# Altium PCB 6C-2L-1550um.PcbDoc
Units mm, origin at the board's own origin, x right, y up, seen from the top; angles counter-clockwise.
Board outline 17.5 x 20 mm, 2 copper layers (Top Layer, Bottom Layer), stack 1.586 mm thick; 22 components, 13 nets, 82 pads, 16 vias.
Unrouted connection lines stored in the file: 1.
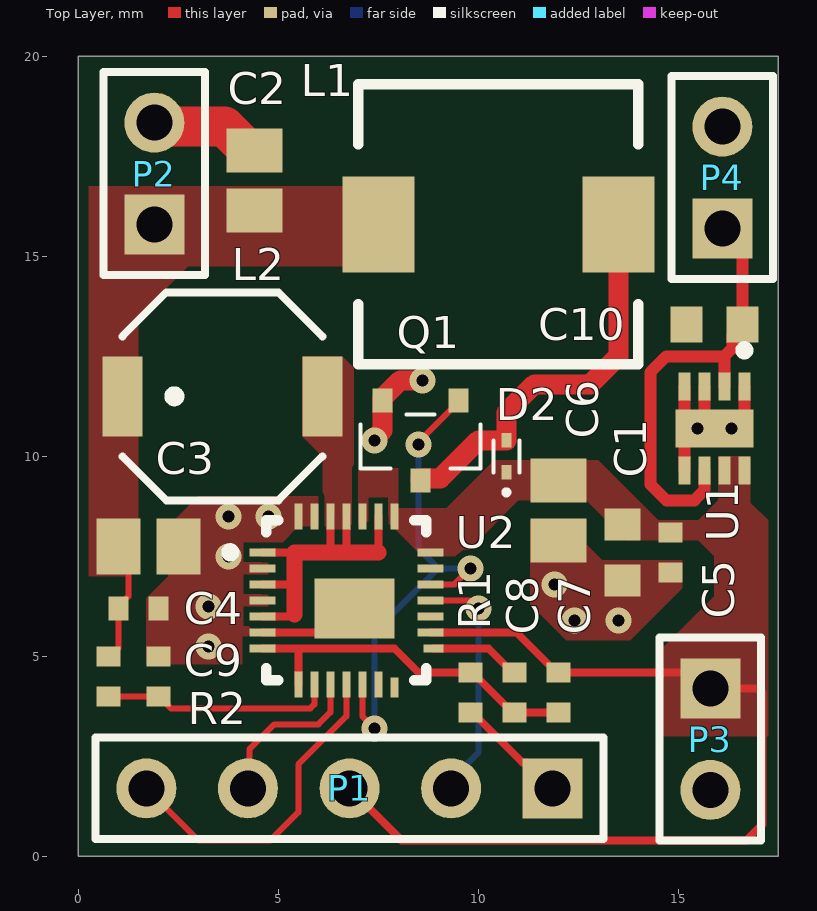
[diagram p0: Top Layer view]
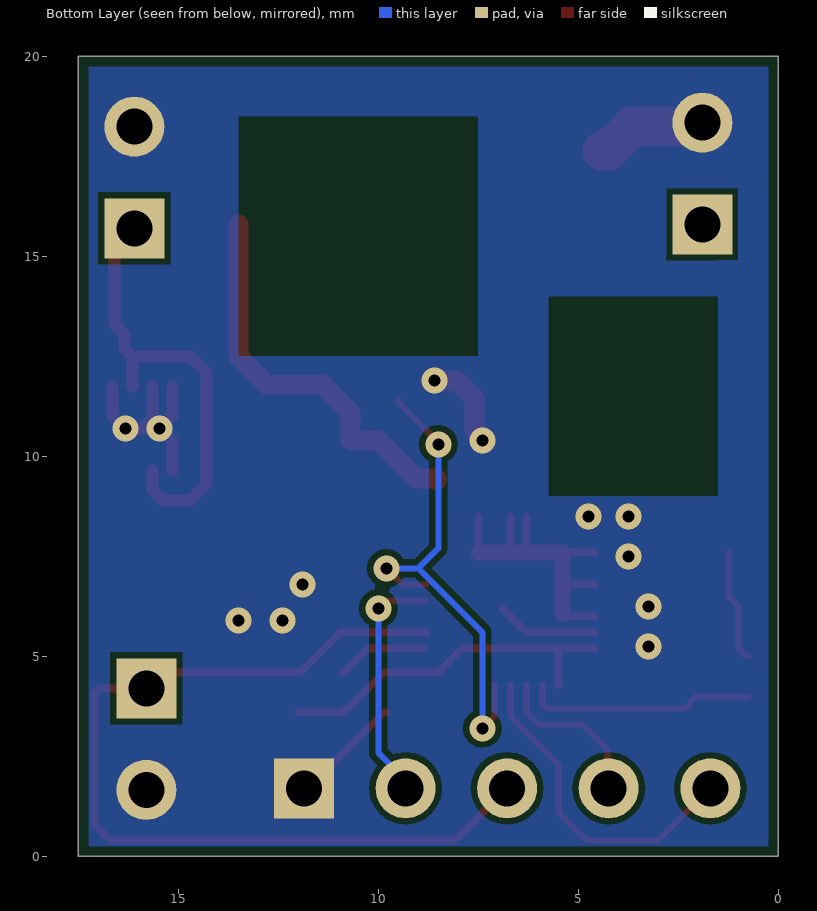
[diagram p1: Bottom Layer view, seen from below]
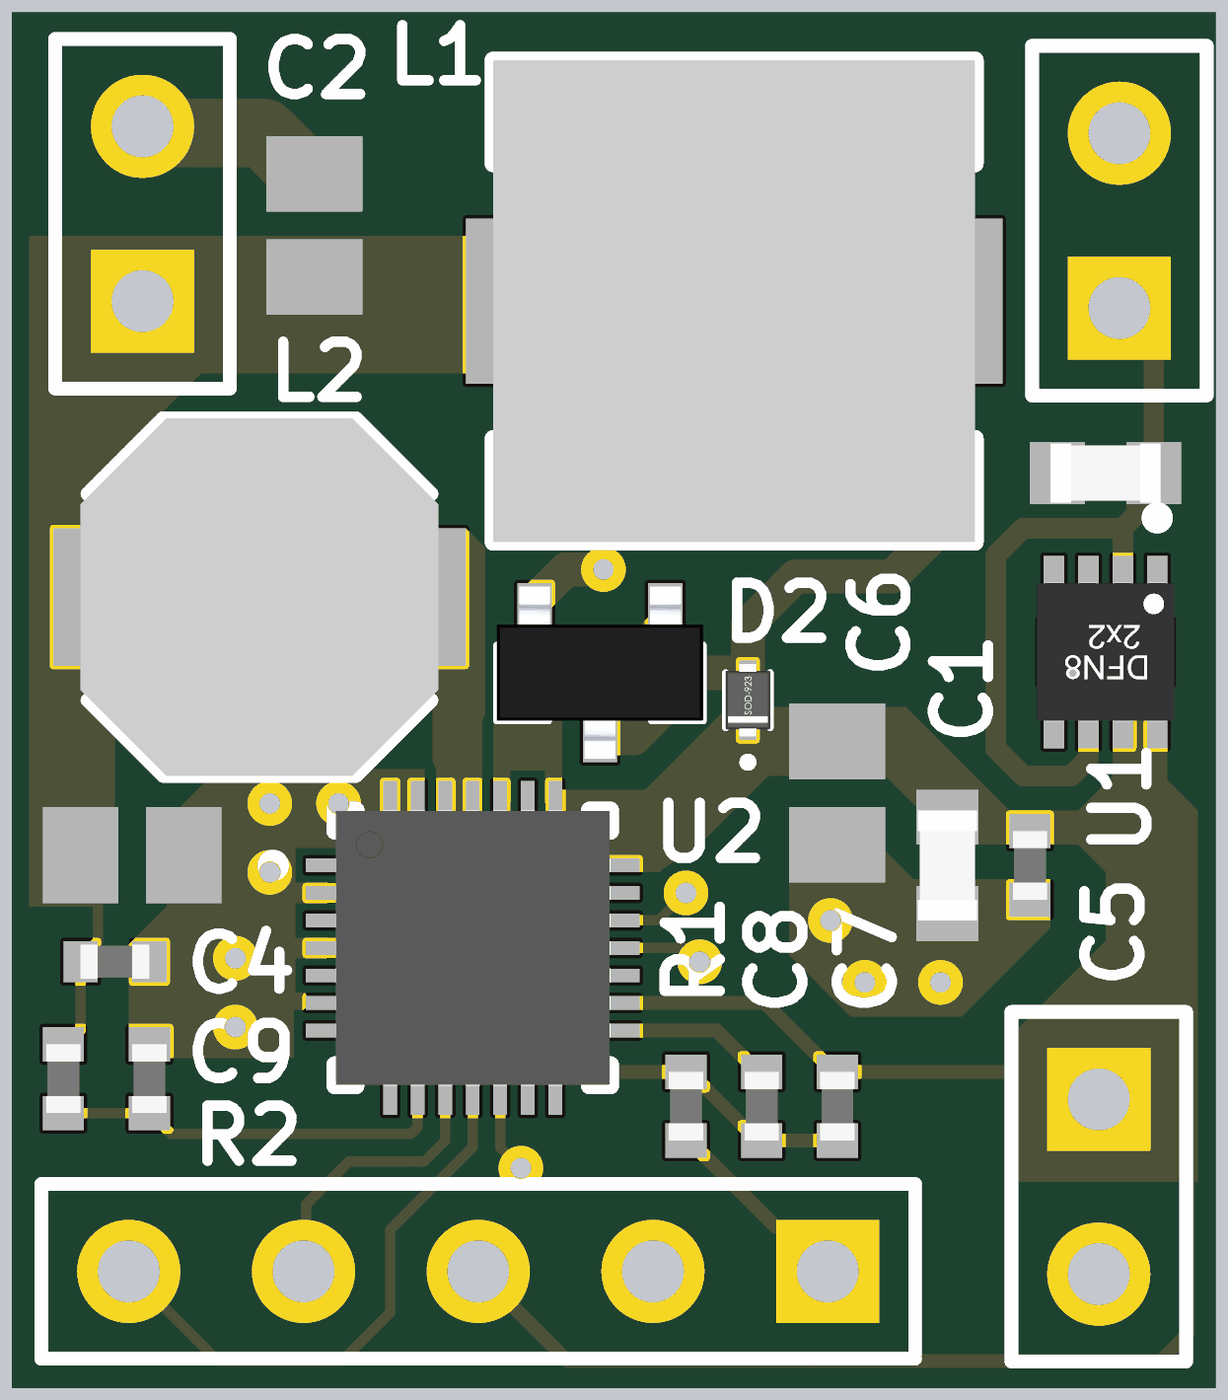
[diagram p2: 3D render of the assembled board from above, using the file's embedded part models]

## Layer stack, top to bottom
Top Solder: solder mask 0.0102, Solder Resist, Dk 3.5
Top Layer: signal copper 0.018
Dielectric1: core 1.55, FR-4, Dk 4.8
Bottom Layer: signal copper 0.018
Bottom Solder: solder mask 0.0102, Solder Resist, Dk 3.5

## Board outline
0,0 17.5,0 17.5,20 0,20

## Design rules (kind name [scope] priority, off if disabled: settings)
BoardOutlineClearance [All] p1: gap=0.25 ignorepadtopadclearanceinfootprint=FALSE except(0: Arc-SplitContinuation Track-SplitContinuation SMDPad-SplitContinuation THPad-SplitContinuation Via-SplitContinuation Fill-SplitContinuation Poly-SplitContinuation Region-SplitContinuation Text-SplitContinuation)
Clearance Clearance-xPP-xTP-xTT [All] p1: gap=0.15 ignorepadtopadclearanceinfootprint=FALSE except(0: Arc-Hole Track-Hole SMDPad-Hole THPad-Hole Via-Hole Fill-Hole Poly-Hole Region-Hole Text-Hole)
ComponentClearance [All] p1: gap=0.25 collisioncheckmode=3 verticalgap=0.25 showdistances=FALSE
DiffPairsRouting [All] p1: maxlimit=0.25 minlimit=0.25 mostfreqgap=0.25 toplayer_minwidth=0.381 toplayer_maxwidth=0.381 toplayer_prefwidth=0.381 bottomlayer_minwidth=0.381 bottomlayer_maxwidth=0.381 bottomlayer_prefwidth=0.381 maxuncoupledlength=12.5
Height [All] p1: minheight=0 maxheight=25 prefheight=12.5
HoleSize HoleSize-PTH [All] p1: absolutevalues=TRUE maxlimit=2 minlimit=0.25 maxpercent=80.000 minpercent=20.000
HoleToHoleClearance [All] p1: gap=0.35 allowstackedmicrovias=TRUE
MinimumAnnularRing "Minimum IAR  >0.45mm" [((ObjectKind = 'Pad') OR (ObjectKind = 'Via')) And (Layer = 'MultiLayer') And (HoleDiameter > AsMM(0.45))] p1: minimumring=0.175 // minimum inner annular ring for pads > 0.45mm finished hole size
MinimumAnnularRing "Minimum IAR <=0.45mm" [((ObjectKind = 'Pad') OR (ObjectKind = 'Via')) And (Layer = 'MultiLayer') And (HoleDiameter <= AsMM(0.45))] p2: minimumring=0.175 // minimum inner annular ring for pads <= 0.45mm finished hole size
MinimumSolderMaskSliver [All] p1: minsoldermaskwidth=0.08
PlaneClearance PlaneClearance-IPI [All] p1: clearance=0.25
PlaneConnect [All] p1: planeconnectstyle=Relief reliefexpansion=0.175 reliefentries=4 reliefconductorwidth=0.2 reliefairgap=0.2
PolygonConnect PolygonConnect-xTW [All] p1: connectstyle=Direct reliefconductorwidth=0.2 reliefentries=4 polygonreliefangle="90 Angle" airgapwidth=0.2
RoutingCorners [All] p1: cornerstyle=45-Degree minsetback=2.5 maxsetback=2.5
RoutingVias "RoutingVias <= 0.45mm" [(ObjectKind = 'Via') And (HoleDiameter <= AsMM(0.45))] p1: holewidth=0.3 width=0.65 viastyle="Through Hole" minholewidth=0.25 minwidth=0.6 maxholewidth=0.45 maxwidth=0.8 // finishet hole size <= 0.45mm
RoutingVias "RoutingVias > 0.45mm" [(ObjectKind = 'Via') And (HoleDiameter > AsMM(0.45))] p2: holewidth=0.5 width=0.85 viastyle="Through Hole" minholewidth=0.5 minwidth=0.85 maxholewidth=0.9 maxwidth=1.25 // finishet hole size > 0.45mm
SilkToSilkClearance [All] p1: silktosilkclearance=0.2
SilkToSolderMaskClearance SilkscreenOverComponentPads [IsPad] p1: minsilkscreentomaskgap=0.2 clearancetoexposedcopper=TRUE
SolderMaskExpansion [All] p1: expansion=0 istentingtop=FALSE
UnRoutedNet [All] p1: checkbadconnections=TRUE
Width Width-xTW [All] p1: maxlimit=1.5 minlimit=0.15 preferedwidth=0.2
18 further rules are at their usual default settings.

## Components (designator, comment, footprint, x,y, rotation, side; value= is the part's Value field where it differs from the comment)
C1 "Cap_0603" 0603 13.6,7.6 r90 top value=2.2uF
C2 "Cap_0805" 0805 4.4,16.9 r270 top value=22uF
C3 "Cap_0805" 0805 1.75,7.75 r180 top value=22uF
C4 "Cap_0402" 0402 1.5,6.2 r180 top value=100nF
C5 "Cap_0402" 0402 14.8,7.6 r90 top value=100nF
C6 "Cap_0805" 0805 12,8.65 r90 top value=22uF
C7 "Cap_0402" 0402 12,4.1 r90 top value=100nF
C8 "Cap_0402" 0402 10.9,4.1 r90 top value=470nF
C9 "Cap_0402" 0402 2,4.5 r270 top value=100nF
C10 "Cap_0603" 0603 15.9,13.3 r0 top value=2.2uF
D2 "NSR0140P2" SOD-923 10.7,9.6 r90 top
L1 "SRR7045-102M" SRR7045-102M 7.5,15.8 r0 top value=X
L2 "SD53-4R7-R" SD53-4R7-R 3.6,11.5 r0 top value=X
P1 "Header 5" HDR1X5 11.86,1.7 r180 top
P2 "Header 2" HDR1X2 1.9,15.8 r90 top
P3 "Header 2" HDR1X2 15.8,4.2 r270 top
P4 "Header 2" HDR1X2 16.1,15.7 r90 top
Q1 "PMV130ENE" SOT-23 9.5,11.4 r180 top
R1 "Res_0402" 0402 9.8,4.1 r270 top value=0
R2 "Res_0402" 0402 0.75,4.5 r270 top value=51K
U1 "MCP1810" VDFN8 16.65,11.75 r270 top
U2 "Sunboost 3" 28-QFN_0.4mm 4.6,7.6 r0 top

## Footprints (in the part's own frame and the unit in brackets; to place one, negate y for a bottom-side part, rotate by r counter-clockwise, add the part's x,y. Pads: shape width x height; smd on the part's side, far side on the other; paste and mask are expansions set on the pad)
28-QFN_0.4mm [mm]
  rect 0.65x0.2 smd mask+0.05: 1(0,0) 2(0,-0.4) 3(0,-0.8) 4(0,-1.2) 5(0,-1.6) 6(0,-2) 7(0,-2.4) 16(4.2,-2) 17(4.2,-1.6) 18(4.2,-1.2) 19(4.2,-0.8) 20(4.2,-0.4) 21(4.2,0)
  rect 0.2x0.65 smd mask+0.05: 8(0.9,-3.3) 9(1.3,-3.3) 10(1.7,-3.3) 11(2.1,-3.3) 12(2.5,-3.3) 13(2.9,-3.3) 22(3.3,0.9) 23(2.9,0.9) 24(2.5,0.9) 25(2.1,0.9) 26(1.7,0.9) 27(1.3,0.9) 28(0.9,0.9)
  rect 0.2x0.5 smd mask+0.05: 14(3.3,-3.375)
  rect 0.5x0.2 smd mask+0.05: 15(4.275,-2.4)
  rect 2x1.5 smd mask+0.05: 29(2.3,-1.4)
  silkscreen extent -0.9,-3.2 4.1,0.8, body extent 0.1,-3.2 4.1,0.8, height 0.75
0402 [mm]
  rect 0.5x0.6 smd mask+0.05: 1(-0.5,0) 2(0.5,0)
  body extent -0.5,-0.25 0.5,0.25, height 0.25
0603 [mm] "0603 footprint"
  rect 0.8x0.9 smd: 1(-0.7,0) 2(0.7,0)
  body extent -0.8,-0.43 0.8,0.43, height 0.48
0805 [mm] "Chip Capacitor, Body 2.0x1.3mm, IPC High Density"
  rect 1.1x1.4 smd: 1(-0.75,0) 2(0.75,0)
  body extent -1.1,-0.72 1.1,0.72, height 1.4
HDR1X2 [mm] "Connector; Header; 2 Position"
  rect 1.5x1.5 hole 0.9: 1(0,0)
  round 1.5 hole 0.9: 2(2.54,0)
  silkscreen extent -1.27,-1.27 3.81,1.27
HDR1X5 [mm] "Connector; Header; 5 Position"
  rect 1.5x1.5 hole 0.9: 1(0,0)
  round 1.5 hole 0.9: 2(2.54,0) 3(5.08,0) 4(7.62,0) 5(10.16,0)
  silkscreen extent -1.27,-1.27 11.43,1.27
SD53-4R7-R [mm]
  rect 1x2 smd mask+0.05: 1(-2.5,0) 2(2.5,0)
  silkscreen extent -2.5,-2.6 2.5,2.6, body extent -2.6,-2.6 2.6,2.6, height 3
SOD-923 [mm]
  rect 0.36x0.25 smd mask+0.05: 1(0,0) 2(0.8,0)
  silkscreen extent -0.52,-0.33 0.8,0.33, body extent -0.12,-0.32 0.93,0.32, height 0.43
SOT-23 [mm]
  rect 0.5x0.6 smd mask+0.05: 1(0,0) 2(1.9,0) 3(0.95,2)
  silkscreen extent -0.55,0.35 2.45,1.7, body extent -0.55,-0.25 2.45,2.25, height 1.1
SRR7045-102M [mm]
  rect 1.8x2.4 smd mask+0.05: 1(0,0) 2(6,0)
  silkscreen extent -0.5,-3.5 6.5,3.5, body extent -0.5,-3.5 6.5,3.5, height 4.5
VDFN8 [mm] "2x2mm"
  rect 0.7x0.3 smd mask+0.05: 1(0,0) 2(0,-0.5) 3(0,-1) 4(0,-1.5) 5(2.1,-1.5) 6(2.1,-1) 7(2.1,-0.5) 8(2.1,0)
  rect 0.95x1.95 smd mask+0.05: 9(1.05,-0.75)
  silkscreen extent -1,-0.1 -0.8,0.1, body extent 0.04,-1.75 2.06,0.25, height 0.95

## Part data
C1 C2 C3 C4 C5 C6 C7 C8 C9 C10: "Capacitor"
D2: "Typical INFRARED GaAs LED"
L1 L2: "Inductor"
P1: "Header, 5-Pin"
P2 P3 P4: "Header, 2-Pin"
Q1: "N-Channel MOSFET"
R1 R2: "Resistor"
U1: "3V Regulator, 150 mA"
U2: "Initvation Sunboost 3"

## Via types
v1: diameter 0.65, hole 0.3, Top Layer to Bottom Layer, 16 vias

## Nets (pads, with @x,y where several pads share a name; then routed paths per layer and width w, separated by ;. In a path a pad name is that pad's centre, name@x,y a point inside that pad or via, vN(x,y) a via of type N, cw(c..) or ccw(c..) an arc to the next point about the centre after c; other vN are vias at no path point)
DGND: C7.1 C8.1 R1.1 U2.7 U2.8 | length 9
  Top Layer w0.2: U2.7 5.5,5.2 ; U2.8 5.5,5.2 ; C7.1 C8.1 10.75,3.75 10.7,3.75 9.85,4.6 R1.1 8.5,4.6 7.9,5.2 5.5,5.2
GND: C1.1 C2.1 C3.1 C4.1 C5.1 C6.1 C9.1 C10.1 P1.1 P2.2 P3.2 P4.2 Q1.2 R1.2 U1.1 U1.3 U1.4 U1.5 U1.9 U2.2 U2.4 U2.6 U2.27 U2.28 U2.29 | length 16.1
  Top Layer w0.2: U2.6 6.3,5.6 U2.29 ; R1.2 9.85,3.6 11.1,2.35 11.21,2.35 P1.1
  Top Layer w0.3: U1.5 15.15,10.375 v1(15.475,10.7) ; U1.4 15.15,11.025 v1(15.475,10.7) ; U1.3 15.65,10.95 U1.9 ; U1.1 16.65,11.025 v1(16.325,10.7) U1.9 ; v1(15.475,10.7) U1.9
  Top Layer w0.5: v1(7.4,10.4) 7.4,10.441 7.6,10.641 7.6,11.45 8.05,11.9 v1(8.6,11.9)
  Top Layer w1: P2.2 1.996,18.244 3.656,18.244 4.25,17.65 C2.1
  other v1: 3.25,5.25 12.4,5.9 13.5,5.9 3.25,6.25 11.9,6.8 3.75,7.5 3.75,8.5 4.75,8.5
ICSP: P1.2 U2.18 | length 6.1
  Top Layer w0.15: U2.18 9.8,6.4 v1(10,6.2)
  Bottom Layer w0.15: P1.2 9.32,1.91 10,2.59 v1(10,6.2)
ICSPCLK: P1.4 U2.10 | length 4.1
  Top Layer w0.15: P1.4 4.275,1.735 4.275,2.675 4.9,3.3 6,3.3 6.3,3.6 U2.10
ICSPDAT: P1.5 U2.11 | length 8.3
  Top Layer w0.15: P1.5 3,0.4 4.8,0.4 5.5,1.1 5.5,2.3 6.7,3.5 U2.11
NetC8_2: C8.2 U2.15 | length 2.3
  Top Layer w0.2: U2.15 10.25,5.2 10.85,4.6 C8.2
NetC9_2: C9.2 R2.2 U2.9 | length 5.8
  Top Layer w0.15: R2.2 2.05,4 2.225,3.825 2.225,3.788 2.313,3.7 5.8,3.7 5.9,3.8 U2.9
NetD2_2: D2.2 L1.2 Q1.3 | length 10
  Top Layer w0.5: Q1.3 8.55,9.45 9.05,9.45 10,10.4 D2.2 10.7,11.1 11.4,11.8 12.8,11.8 13.5,12.5 L1.2
NetL2_2: L2.2 U2.1 U2.3 U2.5 U2.23 U2.25 U2.26 | length 8.8
  Top Layer w0.2: U2.5 5.35,6 5.4,6.05 ; U2.3 5.4,6.8 ; U2.1 5.4,7.6 ; 6.3,7.6 U2.26 ; 6.7,7.6 U2.25 ; 7.5,7.6 U2.23
  Top Layer w0.4: 5.4,6.05 5.4,6.8 5.4,7.6 6.3,7.6 6.7,7.6 7.5,7.6
PWM: Q1.1 U2.12 U2.19 | length 12.7
  Top Layer w0.15: U2.12 7.1,3.5 v1(7.4,3.2) ; v1(8.5,10.3) 8.5,10.35 9.5,11.35 Q1.1 ; U2.19 9.4,6.8 v1(9.8,7.2)
  Bottom Layer w0.15: v1(7.4,3.2) 7.4,5.6 9,7.2 ; v1(8.5,10.3) 8.5,7.7 9,7.2 ; v1(9.8,7.2) 9,7.2
Solar+: C2.2 C3.2 C4.2 L1.1 L2.1 P2.1 R2.1 | length 2.8
  Top Layer w0.15: R2.1 0.8,5 1,5.2 C4.2 1,6.25 1.25,6.5 C3.2@1.25,7.6
VCC: C1.2 C5.2 C6.2 C7.2 D2.1 P1.3 P3.1 U1.7 U1.8 U2.16 U2.21 U2.22 U2.24 | length 23.2
  Top Layer w0.2: P1.3 8.08,0.4 16.7,0.4 17.1,0.8 17.1,4.083 16.983,4.2 P3.1 15.4,4.6 C7.2 11.95,4.6 10.95,5.6 U2.16
VDD: C10.2 P4.1 U1.2 U1.6 | length 11.3
  Top Layer w0.3: U1.6 15.65,9.15 15.4,8.9 14.7,8.9 14.3,9.3 14.3,12.1 14.7,12.5 16.15,12.5 ; P4.1 16.6,15.2 C10.2 16.35,13.05 16.35,12.7 16.15,12.5 ; U1.2 16.15,12.5
pads on no net: U2.13 U2.14 U2.17 U2.20

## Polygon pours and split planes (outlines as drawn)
NetL2_2 on Top Layer "NETL2_2_L01_P012" (solid, pour order 12): 6.6,12.5 6.882,12.218 6.882,8.176 6.115,8.176 6.115,9.985 5.6,10.5 5.6,12.5
GND on Top Layer "GND_L01_P011" (solid, pour order 11): 11.3,8.4 11.3,6.3 12.2,5.4 13.8,5.4 15.1,6.7 15.1,7.4 13.1,7.4 12.7,7.8 12.7,8.4
GND on Top Layer "GND_L01_P001" (solid, pour order 1): 2.25,8.25 2.25,7 1.75,6.5 1.75,6 2.5,6 3,5.5 4.75,5.5 4.75,7.5 5.5,8.25 6,8.25 6,9 3,9
VCC on Top Layer "VCC_L01_P005" (solid, pour order 5): 16,10 16.8,10 16.8,8.845 17.3,8.345 17.3,7.1 16.4,7.1 15.3,8.2 16,8.9
VCC on Top Layer "VCC_L01_P004" (solid, pour order 4): 7,8.3 7,9.7 8,9.7 8,8.7 9.2,8.7 10.4,9.9 13,9.9 14.5,8.4 17.9,8.4 17.9,3 14.5,3 14.5,5.1 15.9,6.5 15.9,7.5 15.5,7.9 13.7,7.9 12.7,8.9 11,8.9 9.6,7.5 8.5,7.5 8.5,7.6 7.8,8.3
GND on Top Layer "GND_L01_P002" (solid, pour order 2): 1.75,6.5 1.7,6.45 1.7,4.8 4.1,4.8 4.1,5.8 3.4,6.5
Solar+ on Top Layer "SOLAR+_L01_P000" (solid, pour order 0): -0.5,16.75 8.25,16.75 8.25,14.75 2.75,14.75 1.5,13.5 1.5,7.25 1.25,7 -0.5,7
GND on Bottom Layer "GND_L02_P008" (solid, pour order 8): 0,20 17.5,20 17.5,0 0,0 0,9 5.75,9 5.75,12.5 13.5,12.5 13.5,18.5 7,18.5 7,14 0,14
GND on Bottom Layer "GND_L02_P010" (solid, pour order 10): 0,20 7.5,20 7.5,11.5 5.75,11.5 5.75,15 0,15
GND on Bottom Layer "GND_L02_P009" (solid, pour order 9): 0,20 1.5,20 1.5,7 0,7

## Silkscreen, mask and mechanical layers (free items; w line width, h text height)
Dimensions:
  the board outline again, w0.1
